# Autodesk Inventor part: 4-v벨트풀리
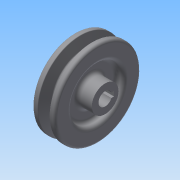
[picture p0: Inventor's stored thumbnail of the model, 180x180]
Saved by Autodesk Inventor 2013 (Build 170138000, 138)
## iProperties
Created: 2015-02
Part Number: 4-v벨트풀리
Material: 일반
Document SubType Name: Modeling
Designer: Administrator
Density: 1 g/cm^3
Author: Administrator
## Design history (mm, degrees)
sketch "스케치1"
  geometry: L1 (0, 0)-(25, 0); L2 (0, 0)-(0, 11); L3 (0, 11)-(6, 11); L4 (6, 11)-(6, 21.5); L5 (6, 21.5)-(0, 21.5); L6 (0, 21.5)-(0, 35.2); L7 (0, 35.2)-(4.675, 35.2); L8 (4.675, 35.2)-(7.426, 26.2); L9 (7.426, 26.2)-(11.574, 26.2); L10 (11.574, 26.2)-(14.325, 35.2); L11 (14.325, 35.2)-(19, 35.2); L12 (19, 35.2)-(19, 21.5); L13 (19, 21.5)-(13, 21.5); L14 (13, 21.5)-(13, 11); L15 (13, 11)-(25, 11); L16 (25, 11)-(25, 0); 4 further points
  constraints: 32 end point, 9 parallel, 5 collinear, 3 equal length, 2 midpoint, 2 perpendicular, 2 point on line, 1 horizontal, 1 horizontal alignment, 1 vertical alignment
  dimensions: "d0" = 25 distance of L1.start L1.end; "d1" = 6.3 distance from line of L9 point (5.5, 32.5); "d2" = 2.7 distance from line of point (5.5, 32.5) L7; "d3" = 65 diameter of point (5.5, 32.5) L1; "d4" = 6 distance of L4.end L5.end; "d5" = 43 diameter of L5 L1; "d6" = 22 diameter of L3 L1; "d7" = 8 distance of point (13.5, 32.5) point (5.5, 32.5); "d8" = 34 deg angle of L10 L8; "d9" = 19 distance between parallel lines of L6 L12
revolve "회전1" sketch "스케치1" stored, may be unused: angle "d10" = 90 deg
sketch "스케치2"
  geometry: L1 (-2, 5.123)-(-2, 7.3); L2 (-2, 7.3)-(2, 7.3); L3 (2, 7.3)-(2, 5.123); C1 r 11 at (0, 0) reference; A1 r 5.5 centre (0, 0) between (-2, 5.123) and (2, 5.123)
  constraints: 6 end point, 2 parallel, 2 point on circle, 1 centre point, 1 coincident, 1 perpendicular, 1 vertical
  dimensions: "d11" = 11 diameter of A1; "d13" = 12.8 dimension on A1 L2; "d14" = 4 distance of L1.end L2.end
extrude "돌출1" cut sketch "스케치2" stored distance "d15" = 10; taper "d16" = 0 deg
fillet "모깎기1" dims "d17" = 1, "d18" = 0.5, "d19" = 2, "d20" = 3
node "솔리드1"
